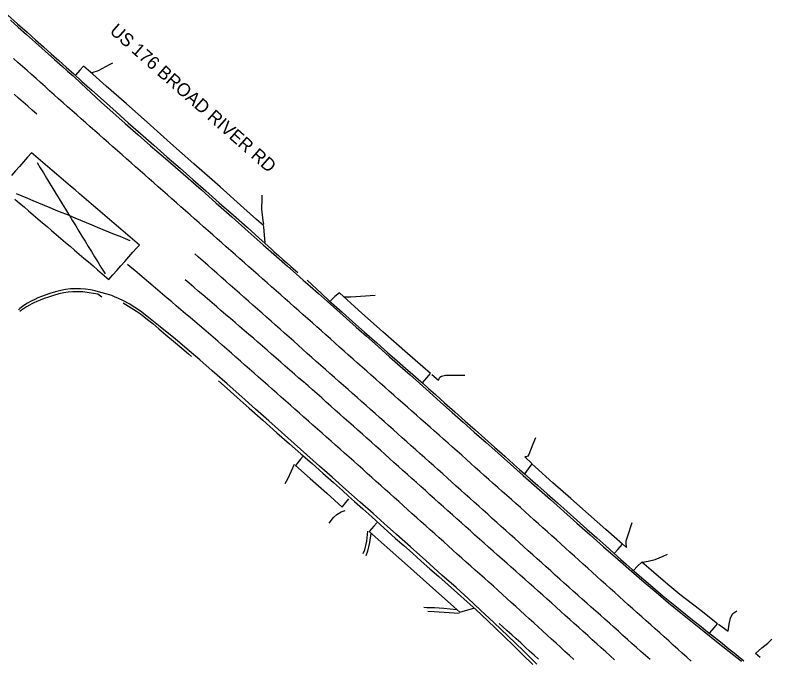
# Model space of a CAD drawing. Extents: x 1970211 to 1973046, y 801032 to 804001.
# Drawn here: x 1970903.4 to 1971216.3, y 803056 to 803321.7 of the extents above; entities that cross this region are included whole.
import ezdxf

# ---------------------------------------------------------------- set-up
doc = ezdxf.new("R2010")
doc.units = 0
for name, color, linetype in [('RD_EX_Conc', 7, 'Continuous'), ('RD_EX_Road', 7, 'Continuous'), ('RD_EX_Road_Paint', 7, 'Continuous'), ('RD_TX_RoadID', 7, 'Continuous')]:
    doc.layers.add(name, color=color, linetype=linetype)

msp = doc.modelspace()

# ---------------------------------------------------------------- linework, layer by layer
at = {"layer": 'RD_EX_Conc'}
for points in [[(1971006.73, 803227.75), (1971006.44, 803230.8), (1971006.19, 803234.16), (1971006.1, 803234.78), (1971003.18, 803237.28), (1970997.97, 803241.93), (1970988.09, 803250.68), (1970977.25, 803260.26), (1970967.66, 803268.8), (1970957.96, 803277.51), (1970949.37, 803284.97), (1970941.05, 803292.39), (1970935.49, 803297.28), (1970931.61, 803300.65), (1970930.1, 803298.92), (1970928.31, 803296.91)], [(1971024.16, 803212.11), (1971030, 803206.66), (1971033.09, 803203.8), (1971035.34, 803201.78), (1971038.65, 803198.86), (1971042.88, 803195.13), (1971047.88, 803190.69), (1971052.95, 803186.18), (1971057.42, 803182.25), (1971061.35, 803178.79), (1971064.84, 803175.71), (1971067.77, 803173.14), (1971070.02, 803171.17), (1971072.04, 803169.4), (1971074.3, 803167.39), (1971077.14, 803164.84), (1971080.94, 803161.45), (1971085.2, 803157.67), (1971089.44, 803153.93), (1971093.58, 803150.27), (1971097.58, 803146.71), (1971101.6, 803143.11), (1971105.81, 803139.34), (1971109.49, 803136.05), (1971111.92, 803133.88), (1971113.94, 803132.1), (1971116.41, 803129.98), (1971119.51, 803127.31), (1971123.44, 803123.88), (1971127.67, 803120.13), (1971131.7, 803116.55), (1971135.69, 803112.97), (1971139.83, 803109.25), (1971143.89, 803105.62), (1971147.62, 803102.31), (1971150.96, 803099.34), (1971153.84, 803096.75), (1971156.04, 803094.78), (1971157.3, 803093.63), (1971158.5, 803092.57), (1971160.53, 803090.84), (1971163.37, 803088.41), (1971167.05, 803085.25), (1971171.36, 803081.59), (1971176.12, 803077.68), (1971180.64, 803074.05), (1971184.23, 803071.21), (1971187.01, 803069.04), (1971189.05, 803067.41), (1971191.38, 803065.54), (1971194.99, 803062.64), (1971198.53, 803059.8), (1971200.65, 803058.1), (1971202.38, 803056.74), (1971204.73, 803054.86)], [(1970939.21, 803205.09), (1970937.52, 803206.37), (1970933.92, 803206.96), (1970931.32, 803207.26), (1970929.26, 803207.36), (1970927.29, 803207.36), (1970925.36, 803207.22), (1970923.45, 803206.93), (1970921.45, 803206.46), (1970919.24, 803205.82), (1970917.12, 803205.14), (1970915.34, 803204.53), (1970913.79, 803203.94), (1970912.31, 803203.34), (1970911.06, 803202.79), (1970910.21, 803202.36), (1970909.36, 803201.87), (1970908.11, 803201.12), (1970906.88, 803200.36), (1970906.05, 803199.81), (1970905.31, 803199.21)], [(1971071.89, 803169.77), (1971073.61, 803171.83), (1971075.16, 803173.64), (1971065.69, 803181.8), (1971055.4, 803190.81), (1971045.39, 803199.75), (1971037.52, 803206.95), (1971035.63, 803205.39), (1971033.81, 803203.62)], [(1970948.08, 803202.73), (1970951.38, 803200.75), (1970953.59, 803199.34), (1970955.17, 803198.24), (1970956.58, 803197.19), (1970958.17, 803195.93), (1970960.26, 803194.21), (1970962.79, 803192.08), (1970965.71, 803189.62), (1970968.9, 803186.93), (1970972.26, 803184.1), (1970975.07, 803181.72), (1970976.33, 803180.63)], [(1970987.47, 803170.52), (1970991.08, 803167.31), (1970995.25, 803163.6), (1971000.12, 803159.28), (1971005.82, 803154.23), (1971011.62, 803149.09), (1971016.79, 803144.54), (1971021.57, 803140.36), (1971026.16, 803136.32), (1971030.61, 803132.4), (1971034.96, 803128.57), (1971038.7, 803125.26), (1971041.27, 803122.94), (1971043.74, 803120.69), (1971047.17, 803117.61), (1971050.9, 803114.27), (1971054.26, 803111.23), (1971057.47, 803108.33), (1971060.71, 803105.44), (1971064.07, 803102.45), (1971067.65, 803099.28), (1971071.3, 803096.05), (1971074.91, 803092.86), (1971078.57, 803089.62), (1971082.41, 803086.23), (1971086.36, 803082.75), (1971090.36, 803079.23), (1971093.89, 803076.09), (1971096.43, 803073.74), (1971098.86, 803071.41), (1971102.05, 803068.3), (1971105.67, 803064.76), (1971109.4, 803061.14), (1971113.29, 803057.35), (1971117.41, 803053.27)], [(1971022.48, 803139.44), (1971021.4, 803138.1), (1971019.35, 803135.61), (1971025.4, 803130.16), (1971032.25, 803124.08), (1971038.59, 803118.26), (1971040.13, 803120.23), (1971041.31, 803121.78)], [(1971151.26, 803099.28), (1971152.63, 803100.9), (1971154.47, 803103.08), (1971147.59, 803109.13), (1971140.5, 803115.41), (1971133.2, 803121.87), (1971125.74, 803128.43), (1971118.38, 803135.03), (1971117.07, 803136.21), (1971115.57, 803134.2), (1971114.08, 803132.27)], [(1971052.98, 803111.85), (1971051.66, 803110.41), (1971049.74, 803108.26), (1971057.22, 803101.62), (1971065.63, 803094.2), (1971074.73, 803086.07), (1971084.76, 803077.12), (1971087.21, 803075), (1971089.62, 803075.68), (1971093, 803076.57)], [(1971047.35, 803099.18), (1971047.95, 803100.66), (1971048.75, 803104.32), (1971049.2, 803108.39)], [(1971190.58, 803066.33), (1971192.42, 803068.42), (1971193.87, 803070.17), (1971186.34, 803076), (1971178.19, 803082.29), (1971173.22, 803086.4), (1971166.45, 803092.25), (1971162.56, 803095.62), (1971160.8, 803093.91), (1971159.15, 803092.18)]]:
    msp.add_lwpolyline(points, dxfattribs=at)
at = {"layer": 'RD_EX_Road'}
for points in [[(1970900.33, 803321.69), (1970904.38, 803318.1), (1970908.29, 803314.64), (1970911.82, 803311.5), (1970915.12, 803308.57), (1970918.31, 803305.73), (1970921.4, 803302.96), (1970924.43, 803300.24), (1970927.58, 803297.42), (1970931.02, 803294.32), (1970935.04, 803290.72), (1970939.9, 803286.37), (1970945.1, 803281.72), (1970950.14, 803277.24), (1970955.27, 803272.71), (1970960.75, 803267.9), (1970966.3, 803263.04), (1970971.63, 803258.39), (1970976.89, 803253.78), (1970982.24, 803249.07), (1970987.79, 803244.17), (1970993.65, 803239.01), (1970999.33, 803234), (1971004.3, 803229.55), (1971007.91, 803226.28), (1971009.51, 803224.81), (1971010.5, 803223.9), (1971012.31, 803222.3), (1971014.26, 803220.58), (1971015.66, 803219.32), (1971017.38, 803217.8), (1971020.31, 803215.3)], [(1970901.39, 803319.63), (1970904.64, 803316.74), (1970908.03, 803313.72), (1970911.85, 803310.32), (1970915.83, 803306.79), (1970919.67, 803303.37), (1970922.91, 803300.5), (1970925.08, 803298.58), (1970927.3, 803296.56), (1970930.69, 803293.42), (1970934.8, 803289.61), (1970939.15, 803285.63), (1970943.83, 803281.4), (1970948.91, 803276.86), (1970954.18, 803272.23), (1970959.41, 803267.72), (1970964.59, 803263.28), (1970969.72, 803258.84), (1970974.96, 803254.27), (1970980.45, 803249.42), (1970986.39, 803244.14), (1970993, 803238.26), (1970999.71, 803232.31), (1971005.97, 803226.78), (1971011.48, 803221.91), (1971015.95, 803217.94), (1971019.58, 803214.73), (1971022.54, 803212.15), (1971025.42, 803209.63), (1971028.81, 803206.6), (1971032.54, 803203.27), (1971036.43, 803199.83), (1971040.41, 803196.32), (1971044.41, 803192.76), (1971048.68, 803188.96), (1971053.44, 803184.75), (1971058.24, 803180.51), (1971062.6, 803176.66), (1971066.67, 803173.06), (1971070.56, 803169.56), (1971074.66, 803165.88), (1971079.33, 803161.74), (1971084.15, 803157.48), (1971088.7, 803153.43), (1971093.26, 803149.37), (1971098.09, 803145.06), (1971103.1, 803140.61), (1971108.21, 803136.09), (1971113.51, 803131.4), (1971119.1, 803126.45), (1971124.75, 803121.44), (1971130.21, 803116.59), (1971135.62, 803111.78), (1971141.11, 803106.91), (1971146.73, 803101.95), (1971152.54, 803096.84), (1971158.23, 803091.88), (1971163.45, 803087.39), (1971168.48, 803083.13), (1971173.58, 803078.85), (1971178.61, 803074.69), (1971183.43, 803070.77), (1971188.28, 803066.89), (1971193.41, 803062.82), (1971198.61, 803058.71), (1971203.7, 803054.68)], [(1970943.67, 803301.83), (1970942.29, 803301.11), (1970937.69, 803298.7), (1970935.02, 803297.82)], [(1971005.45, 803247.26), (1971005.36, 803246.05), (1971005.27, 803241.49), (1971005.75, 803236.72), (1971006.01, 803235.26)], [(1971119.09, 803053.5), (1971113.4, 803059.02), (1971107.23, 803064.97), (1971101.34, 803070.6), (1971095.84, 803075.8), (1971090.68, 803080.56), (1971085.7, 803085.07), (1971079.85, 803090.29), (1971073.18, 803096.24), (1971066.86, 803101.87), (1971061.12, 803107), (1971056.02, 803111.55), (1971051.39, 803115.67), (1971046.09, 803120.38), (1971040.11, 803125.69), (1971034.47, 803130.69), (1971029.28, 803135.27), (1971024.06, 803139.89), (1971018.76, 803144.6), (1971013.48, 803149.28), (1971008.23, 803153.96), (1971002.77, 803158.82), (1970997.08, 803163.91), (1970991.06, 803169.26), (1970984.89, 803174.7), (1970979.73, 803179.21), (1970975.39, 803182.93), (1970969.64, 803187.71), (1970962.67, 803193.39), (1970957.78, 803197.31), (1970955.18, 803199.27), (1970952.85, 803200.86), (1970950.46, 803202.32), (1970948.19, 803203.58), (1970946.11, 803204.59), (1970944.52, 803205.32), (1970943.29, 803205.79), (1970941.4, 803206.38), (1970938.84, 803207.1), (1970936.52, 803207.69), (1970934.53, 803208.09), (1970932.48, 803208.37), (1970930.34, 803208.54), (1970928.25, 803208.59), (1970926.23, 803208.52), (1970924.23, 803208.29), (1970922.21, 803207.9), (1970920.05, 803207.33), (1970917.78, 803206.63), (1970915.82, 803205.97), (1970914.22, 803205.37), (1970912.79, 803204.79), (1970911.45, 803204.2), (1970910.02, 803203.48), (1970908.46, 803202.62), (1970906.91, 803201.62), (1970905.28, 803200.4), (1970904.71, 803199.91)], [(1971039.41, 803205.25), (1971040.58, 803205.2), (1971042.17, 803205.24), (1971052.23, 803205.89)], [(1971075.68, 803173.19), (1971078.39, 803170.8), (1971078.65, 803171.04), (1971078.73, 803171.52), (1971078.98, 803172), (1971079.67, 803172.49), (1971081.3, 803172.83), (1971089.33, 803172.92)], [(1971118.49, 803147.02), (1971117.45, 803144.36), (1971115.79, 803140.07), (1971115.33, 803139.46), (1971114.63, 803139.18), (1971114.18, 803139.17), (1971117.03, 803136.35)], [(1971018.71, 803135.99), (1971017.53, 803133.22), (1971015.98, 803129.95), (1971014.89, 803127.98)], [(1971033.2, 803111.77), (1971035.09, 803114.04), (1971036.43, 803115.34), (1971038.14, 803116.4), (1971039.86, 803117.01)], [(1971158.45, 803111.85), (1971156.56, 803106.41), (1971155.92, 803104.28), (1971155.88, 803103.21), (1971156.04, 803101.93), (1971156.12, 803101.68), (1971154.76, 803102.86)], [(1971050.5, 803107.41), (1971049.92, 803103.7), (1971049.1, 803100.2), (1971048.41, 803098.24)], [(1971162.84, 803095.64), (1971165.17, 803096.02), (1971167.99, 803096.71), (1971171.39, 803098.05), (1971173.1, 803098.87)], [(1971085.82, 803075.92), (1971080.59, 803076.38), (1971076.76, 803076.66), (1971073.58, 803076.77), (1971072.44, 803076.81)], [(1971074.1, 803075.33), (1971076.67, 803075.18), (1971086.94, 803074.5)], [(1971194.24, 803069.94), (1971198.17, 803067.03), (1971198.6, 803069.96), (1971199.22, 803072.59), (1971200.21, 803074.44), (1971201.8, 803075.55)], [(1971211.42, 803056.15), (1971209.58, 803057.91), (1971212.17, 803060.13), (1971214.58, 803062.17), (1971216.3, 803063.84)]]:
    msp.add_lwpolyline(points, dxfattribs=at)
at = {"layer": 'RD_EX_Road_Paint'}
for points in [[(1971182.99, 803054.7), (1971181.13, 803056.36), (1971179.26, 803058.02), (1971177.4, 803059.69), (1971175.53, 803061.35), (1971173.67, 803063.02), (1971171.8, 803064.68), (1971169.93, 803066.34), (1971168.07, 803068.01), (1971166.2, 803069.67), (1971164.34, 803071.33), (1971162.47, 803073), (1971160.61, 803074.66), (1971158.74, 803076.33), (1971156.89, 803078), (1971155.03, 803079.68), (1971153.17, 803081.35), (1971151.32, 803083.03), (1971149.46, 803084.7), (1971147.61, 803086.38), (1971145.75, 803088.05), (1971143.9, 803089.73), (1971142.04, 803091.4), (1971140.19, 803093.08), (1971138.33, 803094.75), (1971136.48, 803096.43), (1971134.62, 803098.1), (1971132.77, 803099.78), (1971130.91, 803101.45), (1971129.05, 803103.13), (1971127.2, 803104.8), (1971125.34, 803106.47), (1971123.47, 803108.14), (1971121.61, 803109.8), (1971119.75, 803111.47), (1971117.88, 803113.14), (1971116.02, 803114.8), (1971114.16, 803116.47), (1971112.29, 803118.14), (1971110.43, 803119.8), (1971108.57, 803121.47), (1971106.7, 803123.14), (1971104.84, 803124.8), (1971102.98, 803126.47), (1971101.11, 803128.14), (1971099.25, 803129.8), (1971097.39, 803131.47), (1971095.52, 803133.13), (1971093.64, 803134.79), (1971091.77, 803136.44), (1971089.9, 803138.1), (1971088.03, 803139.76), (1971086.16, 803141.42), (1971084.29, 803143.08), (1971082.42, 803144.73), (1971080.55, 803146.39), (1971078.67, 803148.05), (1971076.8, 803149.71), (1971074.93, 803151.37), (1971073.06, 803153.02), (1971071.19, 803154.68), (1971069.32, 803156.34), (1971067.45, 803158), (1971065.58, 803159.65), (1971063.71, 803161.31), (1971061.83, 803162.97), (1971059.96, 803164.63), (1971058.09, 803166.29), (1971056.22, 803167.94), (1971054.35, 803169.6), (1971052.48, 803171.26), (1971050.61, 803172.92), (1971048.74, 803174.57), (1971046.86, 803176.23), (1971044.99, 803177.89), (1971043.12, 803179.55), (1971041.25, 803181.21), (1971039.38, 803182.86), (1971037.51, 803184.52), (1971035.64, 803186.18), (1971033.77, 803187.84), (1971031.89, 803189.5), (1971030.02, 803191.15), (1971028.15, 803192.81), (1971026.28, 803194.47), (1971024.41, 803196.13), (1971022.54, 803197.78), (1971020.67, 803199.44), (1971018.8, 803201.1), (1971016.92, 803202.76), (1971015.05, 803204.42), (1971013.18, 803206.07), (1971011.31, 803207.73), (1971009.44, 803209.39), (1971007.57, 803211.05), (1971005.69, 803212.7), (1971003.82, 803214.36), (1971001.94, 803216.01), (1971000.07, 803217.66), (1970998.2, 803219.32), (1970996.32, 803220.97), (1970994.45, 803222.63), (1970992.57, 803224.28), (1970990.7, 803225.93), (1970988.82, 803227.59), (1970986.95, 803229.24), (1970985.07, 803230.9), (1970983.2, 803232.55), (1970981.33, 803234.2), (1970979.45, 803235.86), (1970977.58, 803237.51), (1970975.7, 803239.17), (1970973.83, 803240.82), (1970971.95, 803242.47), (1970970.08, 803244.13), (1970968.2, 803245.78), (1970966.33, 803247.44), (1970964.45, 803249.09), (1970962.58, 803250.74), (1970960.7, 803252.4), (1970958.83, 803254.05), (1970956.95, 803255.7), (1970955.08, 803257.36), (1970953.2, 803259.01), (1970951.33, 803260.67), (1970949.45, 803262.32), (1970947.58, 803263.97), (1970945.7, 803265.63), (1970943.83, 803267.28), (1970941.95, 803268.93), (1970940.08, 803270.59), (1970938.2, 803272.24), (1970936.33, 803273.9), (1970934.45, 803275.55), (1970932.58, 803277.2), (1970930.7, 803278.86), (1970928.83, 803280.51), (1970926.96, 803282.16), (1970925.08, 803283.82), (1970923.21, 803285.47), (1970921.33, 803287.13), (1970919.47, 803288.79), (1970917.6, 803290.46), (1970915.74, 803292.13), (1970913.88, 803293.8), (1970912.02, 803295.46), (1970910.15, 803297.12), (1970908.28, 803298.78), (1970906.41, 803300.44), (1970904.54, 803302.11), (1970902.67, 803303.77)], [(1970912.31, 803280.75), (1970910.44, 803282.41), (1970908.57, 803284.07), (1970906.7, 803285.73), (1970904.83, 803287.39), (1970902.97, 803289.05)], [(1970903.26, 803245.65), (1970905.16, 803244.03), (1970907.06, 803242.4), (1970908.96, 803240.78), (1970910.86, 803239.15), (1970912.76, 803237.53), (1970914.66, 803235.9), (1970916.56, 803234.28), (1970918.46, 803232.65), (1970920.37, 803231.03), (1970922.27, 803229.4), (1970924.17, 803227.78), (1970926.07, 803226.16), (1970927.97, 803224.53), (1970929.87, 803222.91), (1970931.77, 803221.28), (1970933.67, 803219.66), (1970935.57, 803218.03), (1970937.47, 803216.41), (1970939.37, 803214.78), (1970941.27, 803213.16), (1970942.09, 803212.46), (1970943.75, 803214.33), (1970945.41, 803216.19), (1970947.07, 803218.06), (1970948.73, 803219.93), (1970950.39, 803221.8), (1970952.05, 803223.66), (1970953.72, 803225.53), (1970954.74, 803226.68), (1970952.84, 803228.3), (1970950.94, 803229.93), (1970949.04, 803231.55), (1970947.14, 803233.18), (1970945.24, 803234.8), (1970943.34, 803236.43), (1970941.43, 803238.05), (1970939.53, 803239.68), (1970937.63, 803241.3), (1970935.73, 803242.92), (1970933.83, 803244.55), (1970931.93, 803246.17), (1970930.03, 803247.8), (1970928.13, 803249.42), (1970926.23, 803251.05), (1970924.33, 803252.67), (1970922.43, 803254.29), (1970920.53, 803255.92), (1970918.63, 803257.54), (1970916.73, 803259.17), (1970914.83, 803260.79), (1970912.93, 803262.42), (1970911.03, 803264.04), (1970910.1, 803264.83), (1970908.45, 803262.95), (1970906.81, 803261.07), (1970905.16, 803259.19), (1970903.51, 803257.31), (1970901.86, 803255.43)], [(1970912.43, 803260.73), (1970913.73, 803258.6), (1970915.04, 803256.47), (1970916.34, 803254.34), (1970917.65, 803252.2), (1970918.95, 803250.07), (1970920.26, 803247.94), (1970921.56, 803245.81), (1970922.87, 803243.67), (1970924.17, 803241.54), (1970925.48, 803239.41), (1970925.81, 803238.87)], [(1970903.81, 803247.95), (1970906.13, 803247), (1970908.44, 803246.05), (1970910.75, 803245.09), (1970913.06, 803244.14), (1970915.37, 803243.18), (1970917.68, 803242.23), (1970919.99, 803241.27), (1970922.3, 803240.32), (1970924.61, 803239.36), (1970925.81, 803238.87)], [(1970925.81, 803238.87), (1970928.12, 803237.92), (1970930.43, 803236.96), (1970932.74, 803236.01), (1970935.05, 803235.05), (1970937.36, 803234.1), (1970939.67, 803233.14), (1970941.98, 803232.19), (1970944.29, 803231.23), (1970946.6, 803230.28), (1970948.91, 803229.32), (1970950.74, 803228.57)], [(1970925.81, 803238.87), (1970927.11, 803236.74), (1970928.41, 803234.61), (1970929.72, 803232.47), (1970931.02, 803230.34), (1970932.33, 803228.21), (1970933.63, 803226.08), (1970934.94, 803223.94), (1970936.24, 803221.81), (1970937.55, 803219.68), (1970938.85, 803217.55), (1970940.16, 803215.41), (1970940.6, 803214.7)], [(1971165.92, 803055.39), (1971164.05, 803057.05), (1971162.18, 803058.71), (1971160.32, 803060.37), (1971158.45, 803062.03), (1971156.58, 803063.69), (1971154.71, 803065.35), (1971152.84, 803067.01), (1971150.97, 803068.67), (1971149.1, 803070.33), (1971147.24, 803071.99), (1971145.37, 803073.66), (1971143.5, 803075.32), (1971141.63, 803076.98), (1971139.77, 803078.64), (1971137.9, 803080.31), (1971136.04, 803081.97), (1971134.17, 803083.63), (1971132.3, 803085.3), (1971130.44, 803086.96), (1971128.57, 803088.62), (1971126.7, 803090.29), (1971124.84, 803091.95), (1971122.97, 803093.62), (1971121.12, 803095.29), (1971119.26, 803096.97), (1971117.41, 803098.64), (1971115.55, 803100.32), (1971113.7, 803101.99), (1971111.84, 803103.67), (1971109.98, 803105.34), (1971108.13, 803107.02), (1971106.27, 803108.69), (1971104.42, 803110.37), (1971102.56, 803112.04), (1971100.7, 803113.71), (1971098.84, 803115.38), (1971096.98, 803117.05), (1971095.12, 803118.72), (1971093.25, 803120.39), (1971091.39, 803122.05), (1971089.53, 803123.72), (1971087.67, 803125.39), (1971085.81, 803127.06), (1971083.94, 803128.72), (1971082.08, 803130.39), (1971080.22, 803132.06), (1971078.36, 803133.73), (1971076.49, 803135.39), (1971074.62, 803137.06), (1971072.76, 803138.72), (1971070.89, 803140.38), (1971069.03, 803142.05), (1971067.16, 803143.71), (1971065.29, 803145.37), (1971063.43, 803147.04), (1971061.56, 803148.7), (1971059.7, 803150.36), (1971057.83, 803152.03), (1971055.96, 803153.69), (1971054.1, 803155.36), (1971052.23, 803157.02), (1971050.37, 803158.68), (1971048.5, 803160.35), (1971046.63, 803162.01), (1971044.76, 803163.67), (1971042.89, 803165.32), (1971041.02, 803166.98), (1971039.15, 803168.64), (1971037.28, 803170.3), (1971035.41, 803171.96), (1971033.53, 803173.61), (1971031.66, 803175.27), (1971029.79, 803176.93), (1971027.92, 803178.59), (1971026.05, 803180.25), (1971024.18, 803181.9), (1971022.31, 803183.56), (1971020.44, 803185.22), (1971018.56, 803186.88), (1971016.69, 803188.53), (1971014.82, 803190.19), (1971012.95, 803191.85), (1971011.08, 803193.51), (1971009.21, 803195.16), (1971007.33, 803196.82), (1971005.46, 803198.48), (1971003.59, 803200.14), (1971001.72, 803201.79), (1970999.85, 803203.45), (1970997.98, 803205.11), (1970996.11, 803206.77), (1970994.23, 803208.42), (1970992.36, 803210.08), (1970990.49, 803211.74), (1970988.62, 803213.4), (1970986.75, 803215.05), (1970984.87, 803216.7), (1970982.99, 803218.35), (1970981.11, 803220), (1970979.23, 803221.65), (1970977.69, 803223.01)], [(1971134.45, 803055.38), (1971132.6, 803057.06), (1971130.75, 803058.74), (1971128.9, 803060.43), (1971127.05, 803062.11), (1971125.2, 803063.79), (1971123.35, 803065.47), (1971121.5, 803067.15), (1971119.65, 803068.83), (1971117.8, 803070.51), (1971115.95, 803072.19), (1971114.1, 803073.88), (1971112.25, 803075.56), (1971110.4, 803077.24), (1971108.55, 803078.92), (1971106.7, 803080.6), (1971104.85, 803082.28), (1971102.99, 803083.96), (1971101.13, 803085.62), (1971099.26, 803087.29), (1971097.4, 803088.95), (1971095.53, 803090.62), (1971093.67, 803092.29), (1971091.81, 803093.95), (1971089.94, 803095.62), (1971088.08, 803097.28), (1971086.22, 803098.95), (1971084.35, 803100.62), (1971082.49, 803102.28), (1971080.62, 803103.95), (1971078.76, 803105.61), (1971076.9, 803107.28), (1971075.03, 803108.95), (1971073.17, 803110.61), (1971071.31, 803112.28), (1971069.45, 803113.95), (1971067.59, 803115.62), (1971065.72, 803117.29), (1971063.86, 803118.96), (1971062, 803120.63), (1971060.14, 803122.29), (1971058.28, 803123.96), (1971056.42, 803125.63), (1971054.55, 803127.3), (1971052.69, 803128.97), (1971050.83, 803130.64), (1971048.97, 803132.31), (1971047.11, 803133.97), (1971045.25, 803135.64), (1971043.38, 803137.31), (1971041.51, 803138.96), (1971039.64, 803140.62), (1971037.77, 803142.28), (1971035.9, 803143.94), (1971034.02, 803145.6), (1971032.15, 803147.25), (1971030.28, 803148.91), (1971028.41, 803150.57), (1971026.54, 803152.23), (1971024.67, 803153.88), (1971022.8, 803155.54), (1971020.92, 803157.2), (1971019.05, 803158.86), (1971017.18, 803160.51), (1971015.31, 803162.17), (1971013.43, 803163.82), (1971011.55, 803165.47), (1971009.68, 803167.12), (1971007.8, 803168.77), (1971005.92, 803170.43), (1971004.05, 803172.08), (1971002.17, 803173.73), (1971000.29, 803175.38), (1970998.41, 803177.03), (1970996.54, 803178.68), (1970994.66, 803180.33), (1970992.78, 803181.98), (1970990.9, 803183.63), (1970989.03, 803185.28), (1970987.15, 803186.93), (1970985.27, 803188.59), (1970983.38, 803190.22), (1970981.47, 803191.84), (1970979.56, 803193.45), (1970977.66, 803195.07), (1970975.75, 803196.69), (1970973.84, 803198.3), (1970971.94, 803199.92), (1970970.03, 803201.54), (1970968.12, 803203.15), (1970966.22, 803204.77), (1970964.31, 803206.39), (1970962.4, 803208), (1970960.5, 803209.62), (1970958.59, 803211.24), (1970956.68, 803212.85), (1970954.77, 803214.47), (1970952.87, 803216.09), (1970950.96, 803217.7), (1970949.8, 803218.69)], [(1971151.29, 803055.17), (1971149.44, 803056.85), (1971147.58, 803058.52), (1971145.73, 803060.2), (1971143.87, 803061.88), (1971142.02, 803063.55), (1971140.17, 803065.23), (1971138.31, 803066.91), (1971136.46, 803068.59), (1971134.61, 803070.26), (1971132.75, 803071.94), (1971130.89, 803073.61), (1971129.03, 803075.27), (1971127.16, 803076.94), (1971125.3, 803078.61), (1971123.44, 803080.27), (1971121.57, 803081.94), (1971119.71, 803083.61), (1971117.85, 803085.27), (1971115.98, 803086.94), (1971114.12, 803088.61), (1971112.26, 803090.27), (1971110.39, 803091.94), (1971108.52, 803093.59), (1971106.64, 803095.24), (1971104.77, 803096.9), (1971102.89, 803098.55), (1971101.02, 803100.2), (1971099.14, 803101.86), (1971097.27, 803103.51), (1971095.39, 803105.16), (1971093.52, 803106.82), (1971091.65, 803108.48), (1971089.79, 803110.15), (1971087.93, 803111.82), (1971086.06, 803113.48), (1971084.2, 803115.15), (1971082.34, 803116.82), (1971080.47, 803118.48), (1971078.61, 803120.15), (1971076.75, 803121.82), (1971074.88, 803123.48), (1971073.02, 803125.15), (1971071.16, 803126.82), (1971069.29, 803128.48), (1971067.43, 803130.15), (1971065.57, 803131.82), (1971063.71, 803133.49), (1971061.85, 803135.16), (1971059.99, 803136.83), (1971058.13, 803138.5), (1971056.27, 803140.17), (1971054.41, 803141.84), (1971052.55, 803143.51), (1971050.69, 803145.18), (1971048.82, 803146.85), (1971046.96, 803148.52), (1971045.1, 803150.19), (1971043.23, 803151.85), (1971041.36, 803153.5), (1971039.49, 803155.16), (1971037.62, 803156.82), (1971035.75, 803158.48), (1971033.87, 803160.13), (1971032, 803161.79), (1971030.13, 803163.45), (1971028.26, 803165.11), (1971026.39, 803166.76), (1971024.52, 803168.42), (1971022.64, 803170.07), (1971020.75, 803171.71), (1971018.87, 803173.35), (1971016.98, 803174.99), (1971015.09, 803176.63), (1971013.21, 803178.28), (1971011.32, 803179.92), (1971009.44, 803181.56), (1971007.55, 803183.2), (1971005.66, 803184.84), (1971003.78, 803186.48), (1971001.88, 803188.11), (1970999.99, 803189.74), (1970998.09, 803191.37), (1970996.19, 803193), (1970994.3, 803194.63), (1970992.4, 803196.26), (1970990.5, 803197.88), (1970988.61, 803199.51), (1970986.71, 803201.14), (1970984.81, 803202.77), (1970982.92, 803204.4), (1970981.02, 803206.03), (1970979.12, 803207.66), (1970977.23, 803209.28), (1970975.33, 803210.91), (1970973.67, 803212.33)], [(1971119.84, 803055.48), (1971117.99, 803057.16), (1971116.14, 803058.84), (1971114.29, 803060.52), (1971112.44, 803062.2), (1971110.58, 803063.88), (1971108.73, 803065.56), (1971106.88, 803067.24), (1971105.03, 803068.92), (1971103.56, 803070.25)]]:
    msp.add_lwpolyline(points, dxfattribs=at)

# ---------------------------------------------------------------- texts
at = {"layer": 'RD_TX_RoadID'}
msp.add_text('US 176 BROAD RIVER RD', height=5.4, rotation=318.5939, dxfattribs=at).set_placement((1970942.1, 803314.6))

doc.saveas('drawing.dxf')
